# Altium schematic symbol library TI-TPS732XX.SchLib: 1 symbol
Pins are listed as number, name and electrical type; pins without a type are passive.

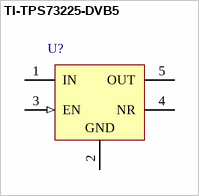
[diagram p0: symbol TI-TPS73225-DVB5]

## TI-TPS73225-DVB5
designator U?
TPS73225/TPS73233 Voltage Regulator
footprint TI-DBV5_N (SOT23, 5-Leads, Body 2.9x1.6mm, Pitch 0.95mm, IPC Medium Density)
pins: 1 IN (power) "Input supply.", 2 GND (power) "Ground.", 3 EN (in) "Driving the enable pin (EN) high turns on the regulator .Driving this pin low puts the regulator into shutdown mode.EN can be connected to IN if not used.", 4 NR "Fixed voltage versions only; connecting an external capacitor to this pin bypasses noise generated by the internal bandgap. This capacitor allows output noise to be reduced to very low levels.", 5 OUT (power) "Output for the regulator. A small capacitor (total typical capacitance >= 2.0uF ceramic) is needed from this pin to ground to assure stability."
